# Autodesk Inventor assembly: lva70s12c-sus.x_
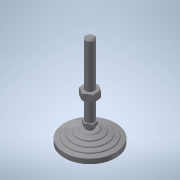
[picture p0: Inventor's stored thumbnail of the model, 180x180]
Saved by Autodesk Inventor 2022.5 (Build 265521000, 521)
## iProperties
Part Number: lva70s12c-sus.x_
Material: 一般
Document SubType Name: Assembly
Designer: ImaoCorp
Sending System: SOLIDWORKS 2017-2017317
MC: AMD64
MC_MODEL: Intel64 Family 6 Model 60 Stepping 3, GenuineIntel
OS: Windows_NT
FRU: Parasolid Version 29.0, build 201,  4-17-2017
FORMAT: text
GUISE: transmit
KEY: lva70s12c-sus
FILE: lva70s12c-sus.x_t
DATE: Mon Jul 01 18:08:08 2019
Author: ImaoCorp
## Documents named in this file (3)
- X:\14_SW2022-Inv2022\00_全2023-1023新製品(TCC)まで\l\lva70s12c-sus\LVA70S12C-SUS.iam
- X:\14_SW2022-Inv2022\00_全2023-1023新製品(TCC)まで\l\lva70s12c-sus\lva70s12c-sus_01.ipt
- X:\14_SW2022-Inv2022\00_全2023-1023新製品(TCC)まで\l\lva70s12c-sus\lva70s12c-sus_02.ipt
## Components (2 placed, 2 different names)
1. lva70s12c-sus_01
2. lva70s12c-sus_02
